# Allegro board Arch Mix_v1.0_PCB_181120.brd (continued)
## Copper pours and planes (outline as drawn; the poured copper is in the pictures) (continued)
VDD_SOC_IN on BOTTOM: 31.72,15.32 31.72,15.01 31.95,14.78 32.44,14.78 32.54,14.68 34.59,14.68 34.7,14.78 34.7,15.09 35.08,15.47 35.31,15.47 35.48,15.65 35.48,16.79 35.31,16.97 33.58,16.97 33.3,16.69 33.3,15.57 33.15,15.42 31.83,15.42
VDD_SOC_IN on PWR04: 33.35,15.29 33.35,20.47 35.38,22.51 36.02,22.51 36.22,22.71 38.28,22.71 38.96,22.02 39.22,22.02 39.42,22.23 39.42,22.4 39.52,22.51 41.27,22.51 41.86,21.92 41.86,20.04 41.07,19.25 38.84,19.25 38.68,19.41 37.01,19.41 36.32,18.72 36.32,16.41 35.03,15.11 33.53,15.11
DCDC_3V3 on TOP: 55.37,29.36 55.37,28.93 55.6,28.7 57.64,28.7 57.84,28.91 57.84,29.57 57.71,29.69 57.1,29.69 56.87,29.47 55.48,29.47
DCDC_3V3 on TOP: 14.36,7.04 16.51,7.04 16.56,6.99 16.56,6.55 16.69,6.43 17.6,6.43 17.68,6.35 17.68,5.54 17.58,5.44 12.04,5.44 11.91,5.56 11.91,6.26 11.91,6.27 11.91,6.38 11.72,6.57 10.16,6.57 10.06,6.67 10.06,8.15 13.24,8.15
DCDC_3V3 on TOP: 7.37,33.63 5.69,33.63 5.56,33.76 5.56,37.77 6.43,38.63 8.05,38.63 8.18,38.51 8.18,36.76 7.49,36.07 7.49,33.76
DCDC_3V3 on BOTTOM: 18.16,6.45 18.59,6.88 18.59,10.69 18.26,11.03 18.26,13.95 18.82,14.5 21.67,14.5 21.77,14.4 21.77,13.84 21.59,13.67 19.41,13.67 19.13,13.39 19.13,11.51 19.86,10.78 19.86,10.66 19.86,10.66 19.86,9.04 20.09,8.82 23.39,8.82 24.31,7.9 24.64,7.9 24.66,7.88 24.66,7.39 24.61,7.34 23.9,7.34 23.04,8.21 20.93,8.21 20.78,8.05 20.78,7.19 20.68,7.09 19.71,7.09 19.38,6.76 19.38,5.82 19,5.44 16.15,5.44 16.1,5.49 16.1,6.38 16.18,6.45
DCDC_3V3 on BOTTOM: 60.63,35.18 59.28,35.18 59.18,35.08 59.18,34.82 58.67,34.32 57.73,34.32 57.61,34.19 57.61,33.15 57.71,33.05 58.72,33.05 59.82,34.14 60.55,34.14 60.81,34.39 60.81,35
DCDC_3V3 on BOTTOM: 13.79,7.19 12.4,7.19 12.27,7.06 12.27,5.89 11.7,5.32 6.9,5.32 6.3,4.73 6.3,1.42 6.45,1.27 8.03,1.27 8.2,1.45 8.2,3.38 9.11,4.28 12.33,4.28 13.84,5.79 13.84,7.14
DCDC_3V3 on LYR03: 15.98,6.3 15.98,5.56 16.1,5.44 17.65,5.44 17.81,5.59 17.81,6.3 17.61,6.49 16.17,6.49
DCDC_3V3 on PWR04: 16.1,5.44 21.46,5.44 25.07,9.04 25.07,10.26 29.97,15.17 31.7,15.17 31.75,15.11 32.46,15.11 33.07,15.72 33.07,20.83 35,22.76 36.02,22.76 36.25,22.99 38.35,22.99 38.58,22.76 41.38,22.76 42.06,22.07 42.06,19.89 40.69,18.52 40.69,13.49 41.2,12.98 48.84,12.98 49.05,13.18 49.5,13.18 49.71,12.98 49.71,11.13 49.52,10.94 49.09,10.94 48.92,11.11 48.92,11.1 41.86,11.1 41.73,10.97 41.73,8.79 42.06,8.46 49.76,8.46 53.39,4.83 57.02,4.83 57.96,5.77 57.96,10.9 61.49,14.43 61.49,34.6 60.27,35.82 54.41,35.82 54.39,35.8 46.72,35.8 45.24,34.32 6.5,34.32 6.49,34.33 5.96,34.33 5.61,33.99 5.61,21.24 8.08,18.77 8.08,17.29 7.77,16.98 6.67,16.98 5.49,15.8 5.49,13.97 13,6.45 13,6 13.14,5.86 15.68,5.86 ; 4 cut-outs
DCDC_OUT on TOP: 33.66,15.55 31.93,15.55 31.45,15.06 30.05,15.06 29.69,14.71 29.24,14.71 29.16,14.63 29.16,14.23 29.26,14.12 29.72,14.12 29.87,13.97 29.87,13.43 30.12,13.17 31.9,13.17 32.8,14.07 33.4,14.07 33.78,14.45 33.78,15.42
DCDC_OUT on BOTTOM: 32.33,14.38 31.98,14.38 31.48,14.87 30.4,14.87 30.14,14.61 30.14,14.12 30.1,14.07 30.1,13.31 30.33,13.08 31.7,13.08 32.38,13.77 32.38,14.3 32.33,14.35
FLASH_VCC on BOTTOM: 25.17,7.88 26.04,7.88 26.11,7.8 26.11,6.45 25.65,6 25.22,6 25.12,6.1 25.12,7.82
FLASH_VCC on BOTTOM: 25.96,11.53 25.55,11.13 25.12,11.13 25.07,11.18 25.07,12.9 25.43,13.26 29.34,13.26 29.59,13.01 29.59,12.19 29.5,12.1 26.2,12.1 25.96,11.86
FLASH_VCC on PWR04: 25.5,9.07 25.5,10.11 30.12,14.73 34.9,14.73 36.6,16.44 36.6,18.72 36.78,18.9 37.13,18.9 37.47,19.23 38.3,19.23 38.33,19.25 38.68,19.25 38.86,19.08 38.86,16.79 37.52,15.44 37.52,13.87 41.05,10.34 41.05,8.66 41.58,8.13 44.53,8.13 44.75,7.9 44.75,6.71 44.35,6.3 41.91,6.3 41.35,6.86 40.67,6.86 37.9,4.09 28.47,4.09 26.57,6 25.15,6 24.84,6.3 24.84,8.43 24.92,8.51 24.94,8.51
LDO_1V8 on BOTTOM: 22.94,12.02 22.78,12.17 22.23,12.17 22.07,12.02 22.07,10.75 22.15,10.67 22.15,9.78 22.23,9.7 22.66,9.7 22.73,9.78 22.73,10.67 23.22,11.15 24.56,11.15 24.66,11.25 24.66,11.61 24.61,11.66 24.31,11.66 23.95,12.02
LDO_3V3 on BOTTOM: 10.01,8.46 9.93,8.54 9.93,8.94 10.41,9.42 10.41,10.95 10.46,11 10.95,11 11.02,10.92 11.02,9.83 11.3,9.55 13.03,9.55 13.26,9.32 15.19,9.32 15.34,9.48 15.34,11.1 15.74,11.5 15.74,14.54 16.59,15.39 21.64,15.39 21.74,15.29 21.74,14.84 21.67,14.76 17.07,14.76 16.48,14.17 16.48,11.36 15.95,10.82 15.95,9.73 16.36,9.32 17.07,9.32 17.2,9.2 17.2,8.92 17.17,8.92 17.04,8.79 15.88,8.79 15.54,8.46
MCU_DCDC_IN_3V3 on BOTTOM: 36.27,18.26 36.42,18.26 36.45,18.29 36.45,18.49 36.37,18.57 35.99,18.57 35.97,18.59 35.46,18.59 35.43,18.62 31.37,18.62 27.1,14.35 23.04,14.35 22.81,14.58 22.81,15.22 22.73,15.29 22.25,15.29 22.17,15.22 22.17,14.02 22.53,13.67 24.36,13.67 24.51,13.51 27.33,13.51 31.64,17.82 35.83,17.82
SDRAM_3V3 on BOTTOM (solid shape): outline of 111 points within 11.73,19.67 19.47,26.34
SDRAM_3V3 on TOP: 22.06,22.32 22,22.38 19.23,22.38 19.1,22.25 19.1,21.57 19.68,20.98 19.68,20.55 19.1,19.97 19.1,19.81 19.35,19.56 20.02,19.56 20.27,19.81 20.27,21.21 20.62,21.57 21.97,21.57 22.06,21.66
USB1_GND on TOP: 4.22,8.97 4.06,8.82 4.06,8.41 4.78,7.7 7.39,7.7 7.57,7.88 7.57,8.66 7.26,8.97
USB2_GND on TOP: 4.34,28.78 5.28,28.78 5.61,29.11 7.57,29.11 7.75,28.93 7.75,28.35 7.62,28.22 6.88,28.22 6.55,27.89 4.42,27.89 4.19,28.12 4.19,28.63
N1428682 on TOP: 32.46,18.49 35.94,18.49 36.27,18.16 36.27,18.01 36.22,17.96 35.41,17.96 34.71,17.26 34.24,17.26 33.74,16.77 32.03,16.77 31.9,16.89 31.9,17.93
N1430764 on TOP: 14.26,12.56 14.61,12.22 14.61,11.71 14.78,11.53 15.98,11.53 16.03,11.48 16.03,11.18 15.98,11.13 14.01,11.13 13.76,11.38 9.44,11.38 9.32,11.5 9.32,12.49 9.39,12.56
N1430772 on TOP: 14.22,10.47 14.81,10.47 14.83,10.49 15.88,10.49 15.93,10.54 15.93,10.8 15.85,10.87 13.94,10.87 13.69,11.12 10.28,11.12 10.11,10.96 10.11,9.67 10.22,9.56 13.32,9.56

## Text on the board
Ref Des/Silkscreen Bottom: 1 | 3V3 | 2 | GND | 3 | 5V | 4 | TXD | RXD | 5 | UART | 22 | 21 | 20 | 19 | J3 | 6 | 7 | 8 | 9 | 10 | 11 | 12 | Designer: John.Xin | 13 | 14 | 15 | 16 | 17 | 18 | SWDIO | SWD | SWDCK | RESET | J4 | RTC-BAT | 3V | SD Card
Ref Des/Silkscreen Top: DC_5V | POWER | J3 | J4 | 3V3 | IN | 1 | GND | 2 | 5V | 3 | v1.0 | UART | 4 | HyperFlash | QSPI Flash | 5 | DEVICE | 6 | SD | 7 | 8 | BOOT_CFG | SW1 PIN: | 0x02_00 | 0x00_00 | 0x00_40 | OFF | 9 | ON | 10 | 0 | 0,1,1,0 | 0,0,1,0 | 1,0,1,0 | 11 | SW1 | AD1 | 12 | AD2 | 13 | AD3 | 14 | AD4 | 15 | SCL | 16 | SDA | 17 | RST | 18 | SWC | RXD | 19 | SWD | TXD | 20 | RGB_LCD | RESET | USER | RGB | 21 | 22 | 50 | HOST | OTG | SWDCK | SWDIO | (OZ) | LAYER 1 - PRIMARY SIDE - SIGNAL | LAYER 2 - GROUND PLANE | LAYER 3 - SIGNAL | LAYER 4 - POWER PLANE | LAYER 5 - GROUND PLANE | LAYER 6 - SECONDARY SIDE - SIGNAL | LAYER# | COPPER WEIGHT | HALF+PLATING | IMPEDANCE CONTROL | +/- 10% | 50ohm SINGLE ENDED | TRACE WIDTH | TRACE WIDTH / SPACE | 90ohm DIFFERENTIAL | 100ohm DIFFERENTIAL | Arch Mix | 4.7/5 | LAYER STACK-UP - ALL DIMENSIONS IN INCHES
User.20: Trace Width | (Mils) | Impedance | (Ohms) | Trace Spacing | "Airgap" | L1 | L3 | L6 | 5.00 | 50 | / | 4.70 | 90 | SCALE: NONE | Layers | Single Ended | Differential | 03-29-18 | QINGFAN.LIU | 1.6MM +/- 10% | LAYER 1  TOP                1 oz | LAYER 2  GROUND PLANE       1 oz. | LAYER 3  SIGNAL PLANE       1 oz. | LAYER 4  POWER PLANE        1 oz | LAYER 5  GROUND PLANE       1 oz. | LAYER 6  BOTTOM             1 oz | FINISHED Cu WEIGHT | 1.0 | DETAIL A | LAYER STACKUP | DETAIL B | IMPEDANCE REQUIREMENTS | IMPEDANCE TOLERANCE IS 10%
User.21: FIGURE | FINISHED_SIZE | 8.0 | 30.0 | 35.0 | 84.0 | 55.12x23.62 | DRILL CHART: TOP to BOTTOM | ALL UNITS ARE IN MILS | TOLERANCE_DRILL | +0.0/-0.0 | +3.0/-3.0 | PLATED | QTY | 17 | 534 | 4 | 44
